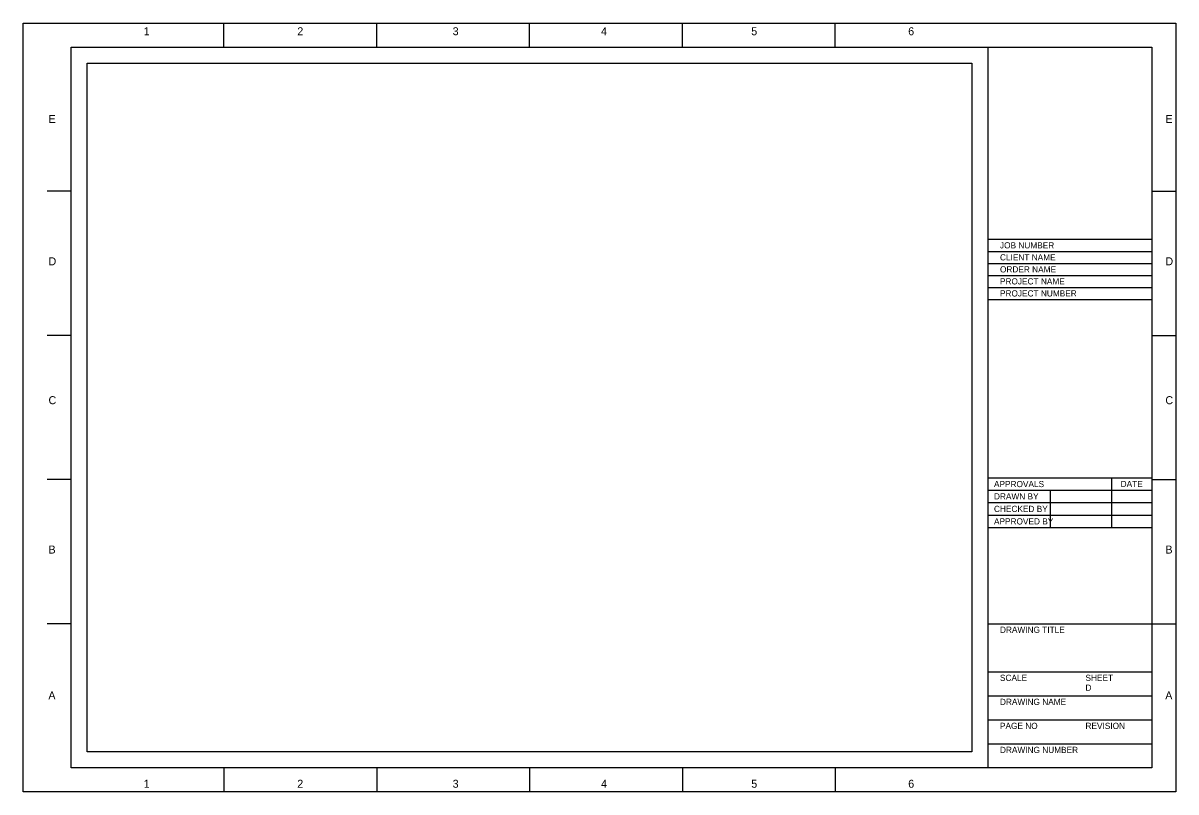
# Model space of a CAD drawing. Extents: x 0 to 3, y 0 to 2.
import ezdxf

# ---------------------------------------------------------------- set-up
doc = ezdxf.new("R2010")
doc.units = 0
for name, color, linetype in [('Border', 7, 'Continuous'), ('BorderPlot', 7, 'Continuous'), ('ClipShape', 7, 'Continuous'), ('TitleBlock', 7, 'Continuous'), ('TitleBlockT', 7, 'Continuous')]:
    doc.layers.add(name, color=color, linetype=linetype)

msp = doc.modelspace()

# ---------------------------------------------------------------- linework, layer by layer
at = {"layer": 'Border'}
for p, q in [((0.5226, 1.9375), (0.5226, 2)), ((0.9203, 1.9375), (0.9203, 2)), ((1.3179, 1.9375), (1.3179, 2)), ((1.7156, 1.9375), (1.7156, 2)), ((2.1132, 1.9375), (2.1132, 2)), ((2.5108, 1.9375), (2.5108, 0.0625)), ((0.125, 1.5625), (0.0625, 1.5625)), ((2.9375, 1.5625), (3, 1.5625)), ((0.125, 1.1875), (0.0625, 1.1875)), ((2.9375, 1.1875), (3, 1.1875)), ((0.125, 0.8125), (0.0625, 0.8125)), ((2.9375, 0.8125), (3, 0.8125)), ((0.125, 0.4375), (0.0625, 0.4375)), ((2.9375, 0.4375), (3, 0.4375)), ((0.5226, 0.0625), (0.5226, 0)), ((0.9203, 0.0625), (0.9203, 0)), ((1.3179, 0.0625), (1.3179, 0)), ((1.7156, 0.0625), (1.7156, 0)), ((2.1132, 0.0625), (2.1132, 0))]:
    msp.add_line(p, q, dxfattribs=at)
msp.add_lwpolyline([(2.9375, 0.0625), (0.125, 0.0625), (0.125, 1.9375), (2.9375, 1.9375)], close=True, dxfattribs=at)
at = {"layer": 'BorderPlot'}
msp.add_lwpolyline([(0, 2), (3, 2), (3, 0), (0, 0)], close=True, dxfattribs=at)
at = {"layer": 'ClipShape'}
for p, q in [((0.1667, 0.1042), (0.1667, 1.8958)), ((0.1667, 1.8958), (2.4692, 1.8958)), ((2.4692, 1.8958), (2.4692, 0.1042)), ((2.4692, 0.1042), (0.1667, 0.1042))]:
    msp.add_line(p, q, dxfattribs=at)
at = {"layer": 'TitleBlock'}
for p, q in [((2.5108, 1.4375), (2.9375, 1.4375)), ((2.5108, 1.4062), (2.9375, 1.4062)), ((2.5108, 1.375), (2.9375, 1.375)), ((2.5108, 1.375), (2.9375, 1.375)), ((2.5108, 1.3437), (2.9375, 1.3437)), ((2.5108, 1.3125), (2.9375, 1.3125)), ((2.5108, 1.3125), (2.9375, 1.3125)), ((2.5108, 1.2812), (2.9375, 1.2812)), ((2.5108, 0.8174), (2.9375, 0.8174)), ((2.8332, 0.6875), (2.8332, 0.8174)), ((2.5108, 0.7849), (2.9375, 0.7849)), ((2.6736, 0.6875), (2.6736, 0.7849)), ((2.5108, 0.7525), (2.9375, 0.7525)), ((2.5108, 0.72), (2.9375, 0.72)), ((2.5108, 0.6875), (2.9375, 0.6875)), ((2.5108, 0.4375), (2.9375, 0.4375)), ((2.5108, 0.3125), (2.9375, 0.3125)), ((2.5108, 0.25), (2.9375, 0.25)), ((2.5108, 0.1875), (2.9375, 0.1875)), ((2.5108, 0.125), (2.9375, 0.125)), ((2.9375, 0.0625), (2.9375, 0.0625)), ((2.9375, 0.0625), (2.9375, 0.0625))]:
    msp.add_line(p, q, dxfattribs=at)

# ---------------------------------------------------------------- texts
at = {"layer": 'Border'}
for s, p in [('1', (0.314, 1.9683)), ('2', (0.7136, 1.9683)), ('3', (1.1179, 1.9683)), ('4', (1.5041, 1.9683)), ('5', (1.8949, 1.9683)), ('6', (2.3033, 1.9683)), ('E', (0.0664, 1.7401)), ('E', (2.9727, 1.7401)), ('D', (0.0663, 1.3698)), ('D', (2.9726, 1.3698)), ('C', (0.0663, 1.0086)), ('C', (2.9726, 1.0086)), ('B', (0.0663, 0.6201)), ('B', (2.9726, 0.6201)), ('A', (0.0659, 0.2407)), ('A', (2.9722, 0.2407)), ('1', (0.314, 0.0109)), ('2', (0.7136, 0.0109)), ('3', (1.1179, 0.0109)), ('4', (1.5041, 0.0109)), ('5', (1.8949, 0.0109)), ('6', (2.3033, 0.0109))]:
    msp.add_text(s, height=0.0208, dxfattribs=at).set_placement(p)
at = {"layer": 'TitleBlockT'}
for s, height, p in [('JOB NUMBER', 0.0161, (2.5421, 1.4138)), ('CLIENT NAME', 0.016098, (2.5421, 1.3826)), ('ORDER NAME', 0.0161, (2.5421, 1.3513)), ('PROJECT NAME', 0.016098, (2.5421, 1.3201)), ('PROJECT NUMBER', 0.016098, (2.5421, 1.2888)), ('APPROVALS', 0.0161, (2.5265, 0.7929)), ('DATE', 0.0161, (2.8561, 0.7931)), ('DRAWN BY', 0.0161, (2.5265, 0.7607)), ('CHECKED BY', 0.0161, (2.5265, 0.7282)), ('APPROVED BY', 0.016098, (2.5265, 0.6957)), ('DRAWING TITLE', 0.016098, (2.5421, 0.4138)), ('SCALE', 0.0161, (2.5421, 0.2888)), ('SHEET', 0.0161, (2.7646, 0.2888)), ('D', 0.0161, (2.7646, 0.2631)), ('DRAWING NAME', 0.016098, (2.5421, 0.2263)), ('PAGE NO', 0.0161, (2.5421, 0.1638)), ('REVISION', 0.0161, (2.7646, 0.1638)), ('DRAWING NUMBER', 0.016098, (2.5421, 0.1013))]:
    msp.add_text(s, height=height, dxfattribs=at).set_placement(p)

doc.saveas('drawing.dxf')
